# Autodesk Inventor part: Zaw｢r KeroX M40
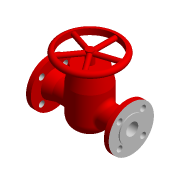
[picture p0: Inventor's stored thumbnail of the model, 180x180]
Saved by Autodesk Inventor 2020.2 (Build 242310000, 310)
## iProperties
Created: 2014-08
Material: Ogólny
Document SubType Name: Modeling
Density: 1 g/cm^3
Appearance: Domyślna
Categories: <MemberInstance><Categories><Category DisplayName="" InternalName="4347fa0f-2144-441d-94cd-e3e15c92b736" Mnemonic="TUBEANDPIPE"><CategoryParameter DisplayName="
Catalog Web Link: www.expertbooks.pl
Designer: F.Stasiak
Manager: www.cadconsulting.pl
Company: Fabian Stasiak CAD Consulting
Author: F.Stasiak
Subject: Zbiór ćwiczeń. Autodesk Inventor 2020. Kurs Professional
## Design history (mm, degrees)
node "Zawór ISO 2531 N 40 DN401"
body "Solid1"
node "Baza1"
